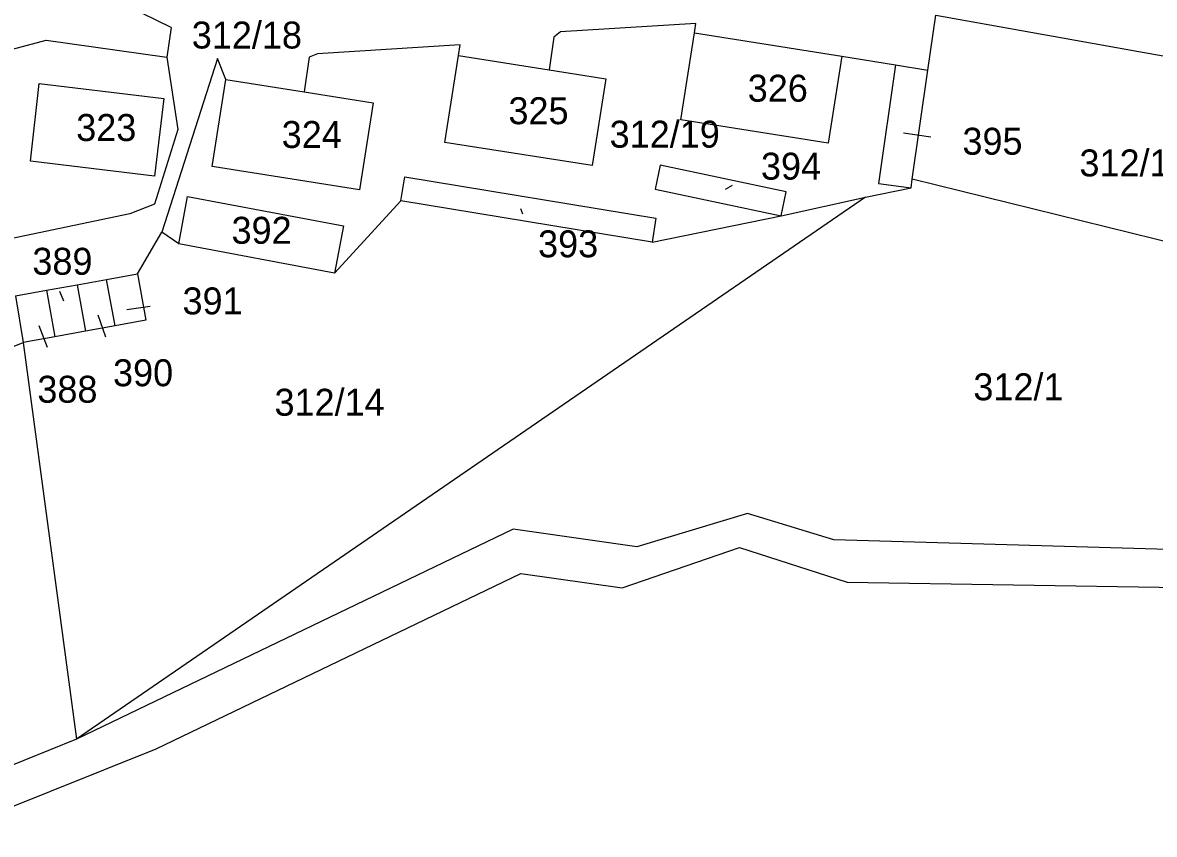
# Model space of a CAD drawing. Extents: x -805826 to -803822, y -1165880 to -1164382.
# Drawn here: x -805401.4 to -805258.6, y -1165073.3 to -1164970.8 of the extents above; entities that cross this region are included whole.
import ezdxf

# ---------------------------------------------------------------- set-up
doc = ezdxf.new("R2010")
doc.units = 0
for name, color, linetype in [('kn_celek - Cisla parcel pomocna', 7, 'Continuous'), ('kn_celek - Cisla pozemkovych parcel', 7, 'Continuous'), ('kn_celek - Cisla stavebnich parcel', 7, 'Continuous'), ('kn_celek - Hranice parcel', 7, 'Continuous'), ('kn_celek - Vnitrni kresby', 7, 'Continuous')]:
    doc.layers.add(name, color=color, linetype=linetype)

msp = doc.modelspace()

# ---------------------------------------------------------------- linework, layer by layer
at = {"layer": 'kn_celek - Cisla parcel pomocna'}
for p, q in [((-805290.25, -1164984.75), (-805286.81, -1164985.24)), ((-805312.72, -1164991.84), (-805311.84, -1164991.34)), ((-805338.6, -1164994.26), (-805338.34, -1164994.95)), ((-805396.23, -1165005.98), (-805396.74, -1165004.75)), ((-805388.28, -1165007.03), (-805385.36, -1165006.59)), ((-805391.95, -1165007.68), (-805391.01, -1165010.46)), ((-805399.39, -1165009.03), (-805398.34, -1165011.78))]:
    msp.add_line(p, q, dxfattribs=at)
at = {"layer": 'kn_celek - Hranice parcel'}
for p, q in [((-805382.7, -1164971.43), (-805388.22, -1164968.76)), ((-805316.48, -1164970.94), (-805333.58, -1164972)), ((-805316.65, -1164972.12), (-805316.48, -1164970.94)), ((-805287.19, -1164976.81), (-805286.2, -1164969.87)), ((-805286.2, -1164969.87), (-805233.69, -1164979.3)), ((-805382.7, -1164971.43), (-805383.23, -1164975.2)), ((-805333.58, -1164972), (-805334.42, -1164972.66)), ((-805318.39, -1164983.09), (-805316.65, -1164972.12)), ((-805316.65, -1164972.12), (-805298.05, -1164975.07)), ((-805408.45, -1164975.7), (-805398.47, -1164973.02)), ((-805398.47, -1164973.02), (-805383.23, -1164975.2)), ((-805346.24, -1164973.61), (-805364.23, -1164974.76)), ((-805346.43, -1164974.96), (-805346.24, -1164973.61)), ((-805334.42, -1164972.66), (-805335.01, -1164976.77)), ((-805365.29, -1164975.19), (-805365.92, -1164979.56)), ((-805364.23, -1164974.76), (-805365.29, -1164975.19)), ((-805348.17, -1164985.93), (-805346.43, -1164974.96)), ((-805346.43, -1164974.96), (-805335.01, -1164976.77)), ((-805298.05, -1164975.07), (-805299.78, -1164986.03)), ((-805298.05, -1164975.07), (-805291.28, -1164976.16)), ((-805376.85, -1164975.37), (-805383.87, -1164997.28)), ((-805375.79, -1164978), (-805376.85, -1164975.37)), ((-805291.28, -1164976.16), (-805293.42, -1164991.11)), ((-805291.28, -1164976.16), (-805287.19, -1164976.81)), ((-805377.53, -1164988.97), (-805375.79, -1164978)), ((-805375.79, -1164978), (-805365.92, -1164979.56)), ((-805335.01, -1164976.77), (-805327.83, -1164977.91)), ((-805327.83, -1164977.91), (-805329.57, -1164988.87)), ((-805289.16, -1164990.57), (-805287.19, -1164976.81)), ((-805400.45, -1164988.3), (-805399.36, -1164978.5)), ((-805399.36, -1164978.5), (-805383.61, -1164980.4)), ((-805383.61, -1164980.4), (-805384.79, -1164990.2)), ((-805365.92, -1164979.56), (-805357.19, -1164980.95)), ((-805357.19, -1164980.95), (-805358.93, -1164991.91)), ((-805299.78, -1164986.03), (-805318.39, -1164983.09)), ((-805329.57, -1164988.87), (-805348.17, -1164985.93)), ((-805384.79, -1164990.2), (-805400.45, -1164988.3)), ((-805358.93, -1164991.91), (-805377.53, -1164988.97)), ((-805320.99, -1164988.83), (-805321.61, -1164991.84)), ((-805305.09, -1164992.19), (-805320.99, -1164988.83)), ((-805353.7, -1164993.32), (-805353.23, -1164990.27)), ((-805353.23, -1164990.27), (-805321.52, -1164995.51)), ((-805289.32, -1164991.69), (-805289.16, -1164990.57)), ((-805228.14, -1165005.65), (-805289.16, -1164990.57)), ((-805321.61, -1164991.84), (-805305.72, -1164995.19)), ((-805305.72, -1164995.19), (-805305.09, -1164992.19)), ((-805295.07, -1164992.86), (-805289.32, -1164991.69)), ((-805293.42, -1164991.11), (-805289.32, -1164991.69)), ((-805295.07, -1164992.86), (-805394.66, -1165061.25)), ((-805381.74, -1164998.73), (-805380.65, -1164992.77)), ((-805380.65, -1164992.77), (-805360.96, -1164996.48)), ((-805362.07, -1165002.42), (-805353.7, -1164993.32)), ((-805322.01, -1164998.52), (-805353.7, -1164993.32)), ((-805305.72, -1164995.19), (-805295.07, -1164992.86)), ((-805322.01, -1164998.52), (-805305.72, -1164995.19)), ((-805360.96, -1164996.48), (-805362.07, -1165002.42)), ((-805321.52, -1164995.51), (-805322.01, -1164998.52)), ((-805386.97, -1165002.52), (-805383.87, -1164997.28)), ((-805381.74, -1164998.73), (-805383.87, -1164997.28)), ((-805362.07, -1165002.42), (-805381.74, -1164998.73)), ((-805394.56, -1165003.9), (-805390.86, -1165003.23)), ((-805390.86, -1165003.23), (-805386.97, -1165002.52)), ((-805389.78, -1165009.07), (-805390.86, -1165003.23)), ((-805386.97, -1165002.52), (-805385.9, -1165008.36)), ((-805402.36, -1165005.32), (-805398.43, -1165004.6)), ((-805398.43, -1165004.6), (-805394.56, -1165003.9)), ((-805398.43, -1165004.6), (-805397.39, -1165010.46)), ((-805394.56, -1165003.9), (-805393.52, -1165009.75)), ((-805402.36, -1165005.32), (-805401.37, -1165011.19)), ((-805389.78, -1165009.07), (-805393.52, -1165009.75)), ((-805385.9, -1165008.36), (-805389.78, -1165009.07)), ((-805397.39, -1165010.46), (-805401.37, -1165011.19)), ((-805393.52, -1165009.75), (-805397.39, -1165010.46)), ((-805412.96, -1165015.8), (-805401.37, -1165011.19)), ((-805401.37, -1165011.19), (-805394.66, -1165061.25)), ((-805309.96, -1165032.77), (-805323.94, -1165036.97)), ((-805299.06, -1165036.1), (-805309.96, -1165032.77)), ((-805339.52, -1165034.75), (-805394.66, -1165061.25)), ((-805323.94, -1165036.97), (-805339.52, -1165034.75)), ((-805192.86, -1165039.19), (-805299.06, -1165036.1)), ((-805325.79, -1165042.15), (-805310.98, -1165037.08)), ((-805310.98, -1165037.08), (-805297.37, -1165041.45)), ((-805384.61, -1165062.47), (-805338.55, -1165040.33)), ((-805338.55, -1165040.33), (-805325.79, -1165042.15)), ((-805297.37, -1165041.45), (-805192.4, -1165043.05)), ((-805394.66, -1165061.25), (-805413.81, -1165068.97)), ((-805411.54, -1165073.26), (-805384.61, -1165062.47))]:
    msp.add_line(p, q, dxfattribs=at)
at = {"layer": 'kn_celek - Vnitrni kresby'}
for p, q in [((-805383.23, -1164975.2), (-805381.88, -1164984.3)), ((-805381.88, -1164984.3), (-805384.79, -1164993.73)), ((-805384.79, -1164993.73), (-805387.94, -1164994.94)), ((-805387.94, -1164994.94), (-805403.8, -1164998.29))]:
    msp.add_line(p, q, dxfattribs=at)

# ---------------------------------------------------------------- texts
at = {"layer": 'kn_celek - Cisla parcel pomocna'}
for s, p in [('395', (-805282.83, -1164987.49)), ('394', (-805308.26, -1164990.64)), ('393', (-805336.39, -1165000.44)), ('389', (-805400.22, -1165002.64)), ('391', (-805381.27, -1165007.64)), ('390', (-805390.04, -1165016.71)), ('388', (-805399.59, -1165018.79))]:
    msp.add_text(s, height=3.4, dxfattribs=at).set_placement(p)
at = {"layer": 'kn_celek - Cisla pozemkovych parcel'}
for s, p in [('312/18', (-805380.1, -1164974.09)), ('312/19', (-805327.36, -1164986.6)), ('312/16', (-805268.06, -1164990.23)), ('312/1', (-805281.45, -1165018.48)), ('312/14', (-805369.66, -1165020.43))]:
    msp.add_text(s, height=3.4, dxfattribs=at).set_placement(p)
at = {"layer": 'kn_celek - Cisla stavebnich parcel'}
for s, height, p in [('326', 3.4, (-805309.93, -1164980.8)), ('325', 3.4, (-805340.13, -1164983.64)), ('323', 3.4, (-805394.69, -1164985.76)), ('324', 3.4, (-805368.75, -1164986.64)), ('395', 0.005, (-805290.25, -1164984.75)), ('394', 0.005, (-805312.72, -1164991.84)), ('393', 0.005, (-805338.6, -1164994.26)), ('392', 3.4, (-805375.08, -1164998.73)), ('389', 0.005, (-805396.23, -1165005.98)), ('390', 0.005, (-805391.95, -1165007.68)), ('391', 0.005, (-805388.28, -1165007.03)), ('388', 0.005, (-805399.39, -1165009.03))]:
    msp.add_text(s, height=height, dxfattribs=at).set_placement(p)

doc.saveas('drawing.dxf')
